// Mitsubishi GX Works2 project: MC-20MR-4MTS-F430-FX-2C   PLC: FX1S

PROGRAM MAIN
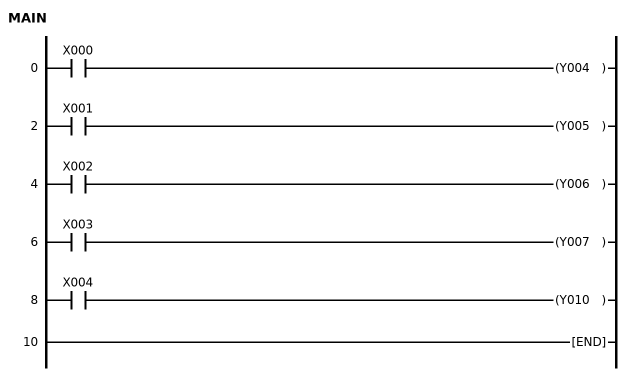
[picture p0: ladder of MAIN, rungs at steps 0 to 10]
0     LD      X000
      OUT     Y004
2     LD      X001
      OUT     Y005
4     LD      X002
      OUT     Y006
6     LD      X003
      OUT     Y007
8     LD      X004
      OUT     Y010
10    END
END_PROGRAM
